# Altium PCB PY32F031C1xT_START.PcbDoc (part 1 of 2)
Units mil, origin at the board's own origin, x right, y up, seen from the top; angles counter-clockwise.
Board outline 1771.65 x 3929.06 mil, 2 copper layers (Top Layer, Bottom Layer), stack 21 mil thick; 137 components, 144 nets, 525 pads, 269 vias.
Unrouted connection lines stored in the file: 5.
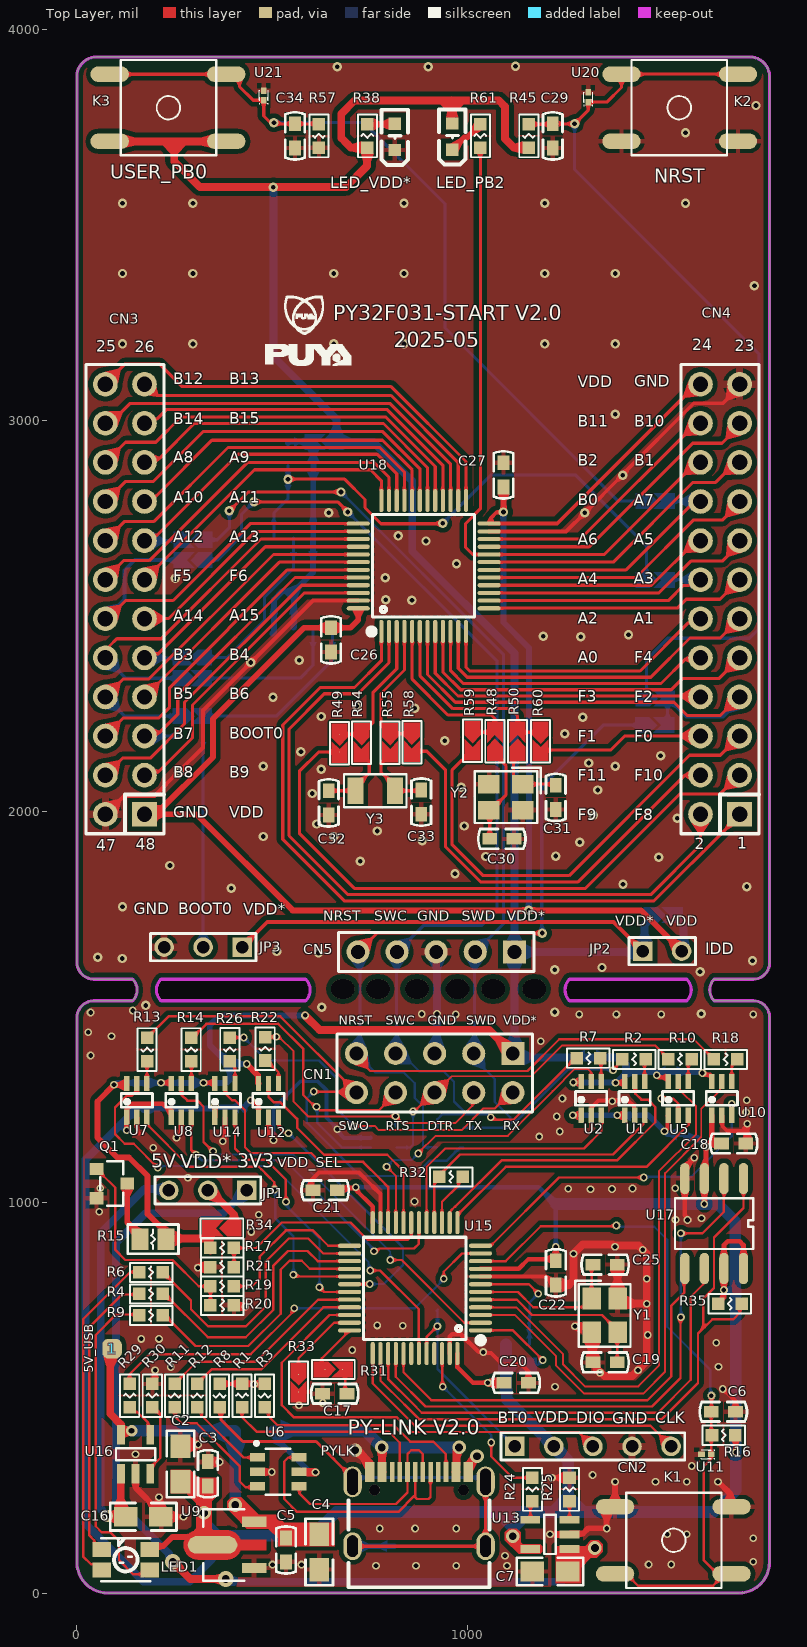
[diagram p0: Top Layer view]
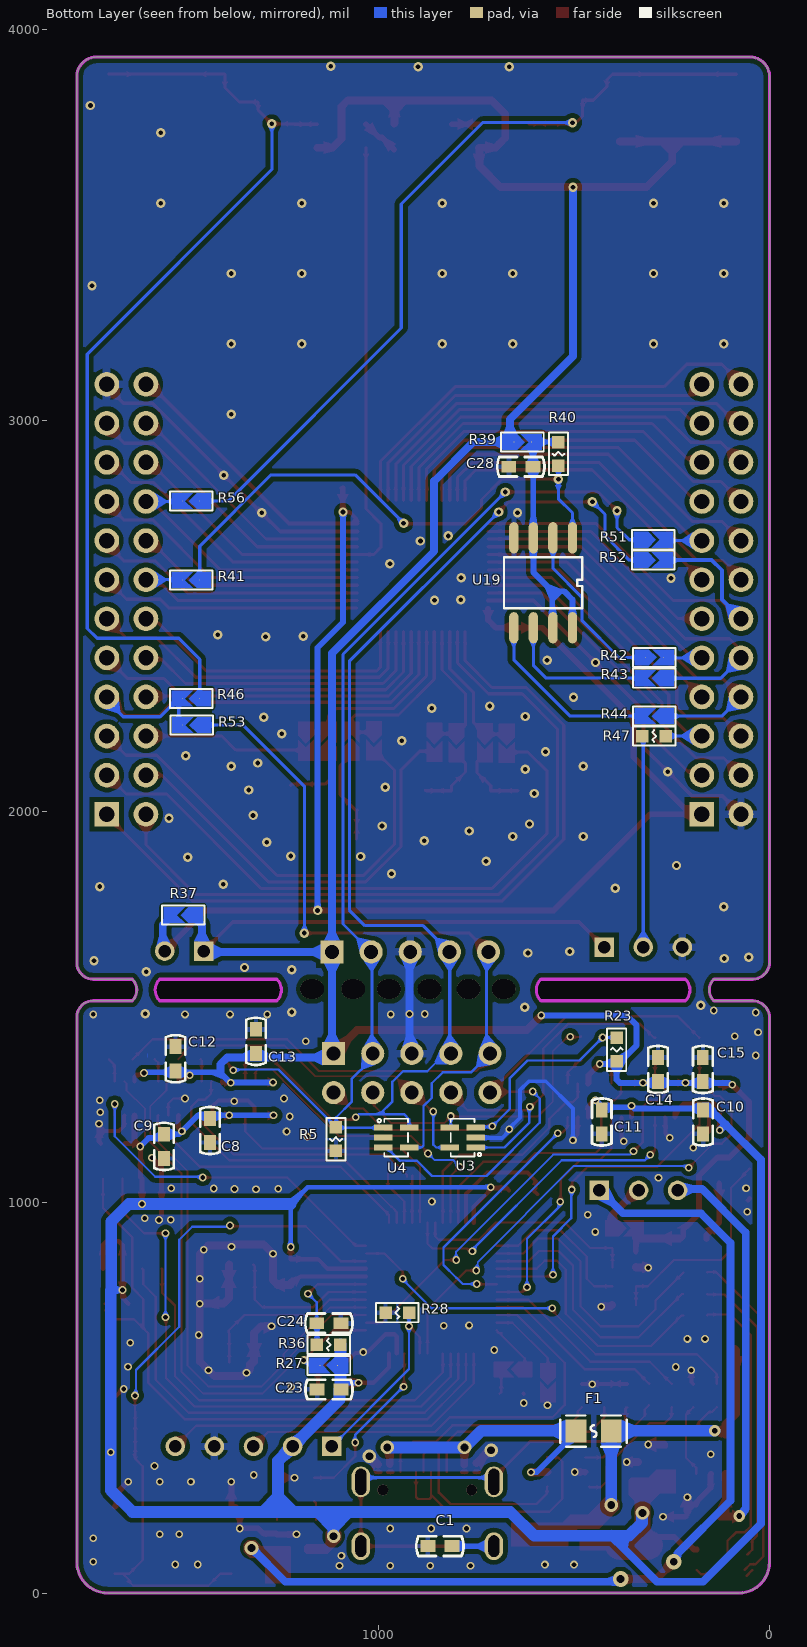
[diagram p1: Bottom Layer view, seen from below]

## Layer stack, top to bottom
Top Solder: solder mask 0.4, Solder Resist, Dk 3.5
Top Layer: signal copper 1.4
Dielectric 2: prepreg 2.8, Composite dielectric, Dk 4.1
Dielectric 1: prepreg 12.6, Composite dielectric, Dk 4.1
Dielectric 3: prepreg 2.8, Composite dielectric, Dk 4.1
Bottom Layer: signal copper 1.4
Bottom Solder: solder mask 0.4, Solder Resist, Dk 3.5

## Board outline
0,78.74 0,1470 cw(c43.75,1471.25) 42.5,1515 142.5,1515 ccw(c115,1542.5) 142.5,1570 42.5,1570 cw(c43.75,1613.75) 0,1615 0,3879.06 cw(c50,3879.06) 50,3929.06 1721.65,3929.06 cw(c1721.65,3879.06) 1771.65,3879.06 1771.65,1611.65 cw(c1730,1611.65) 1730,1570 1630,1570 ccw(c1657.5,1542.5) 1630,1515 1730,1515 cw(c1730,1473.35) 1771.65,1473.35 1771.65,78.74 cw(c1692.91,78.74) 1692.91,0 78.74,0 cw(c78.74,78.74)
cut-out: 1260,1515 cw(c1287.5,1542.5) 1260,1570 1560,1570 cw(c1532.5,1542.5) 1560,1515
cut-out: 215,1515 cw(c242.5,1542.5) 215,1570 585,1570 cw(c557.5,1542.5) 585,1515
cut-out: 215,1515 cw(c242.5,1542.5) 215,1570 585,1570 cw(c557.5,1542.5) 585,1515 565,1515
cut-out: 1260,1515 cw(c1287.5,1542.5) 1260,1570 1560,1570 cw(c1532.5,1542.5) 1560,1515

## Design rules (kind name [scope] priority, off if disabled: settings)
Clearance polygon [InPolygon] p1: gap=12 ignorepadtopadclearanceinfootprint=TRUE
Clearance [All] p2: gap=8 ignorepadtopadclearanceinfootprint=TRUE
HoleToHoleClearance [All] p1: gap=1 allowstackedmicrovias=TRUE
MinimumSolderMaskSliver [All] p1: minsoldermaskwidth=0
PlaneClearance [All] p1: clearance=8
PlaneConnect [All] p1: planeconnectstyle=Direct reliefexpansion=20 reliefentries=4 reliefconductorwidth=10 reliefairgap=10
PolygonConnect [All] p1: thpad.connectstyle=Relief thpad.reliefconductorwidth=20 thpad.reliefentries=4 thpad.polygonreliefangle="90 Angle" thpad.airgapwidth=10 smdpad.connectstyle=Relief smdpad.reliefconductorwidth=12 smdpad.reliefentries=4 smdpad.polygonreliefangle="90 Angle" smdpad.airgapwidth=10 via.connectstyle=Direct via.reliefconductorwidth=10 via.reliefentries=4 via.polygonreliefangle="90 Angle" via.airgapwidth=10
RoutingVias [All] p1: holewidth=28 width=50 viastyle="Through Hole" minholewidth=28 minwidth=50 maxholewidth=28 maxwidth=50
SilkToSilkClearance [All] p1: silktosilkclearance=0
SilkToSolderMaskClearance [IsPad] p1: minsilkscreentomaskgap=0 clearancetoexposedcopper=TRUE
SolderMaskExpansion [All] p1: expansion=4 istentingtop=FALSE
UnRoutedNet [All] p1: checkbadconnections=TRUE
Width [All] p1: maxlimit=100 minlimit=5 preferedwidth=8
23 further rules are at their usual default settings.

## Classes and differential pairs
component class PY32F031C1xT_START: 3 C26 C27 C28 C29 C30 C31 C32 C33 C34 CN3 CN4 CN5 JP2 JP3 K2 K3 LED_PB2 LED_VDD* R37 R38 R39 R40 R41 R42 R43 R44 R45 R46 R47 R48 R49 R50 R51 R52 R53 R54 R55 R56 R57 R58 R59 R60 R61 U18 U19 U20 U21 Y2 Y3
component class PY32F403C1xT_LINK: 1 C1 C2 C3 C4 C5 C6 C7 C8 C9 C10 C11 C12 C13 C14 C15 C16 C17 C18 C19 C20 C21 C22 C23 C24 C25 CN1 CN2 F1 JP1 K1 LED1 PYLK Q1 R1 R2 R3 R4 R5 R6 R7 R8 R9 R10 R11 R12 R13 R14 R15 R16 R17 R18 R19 R20 R21 R22 R23 R24 R25 R26 R27 R28 R29 R30 R31 R32 R33 R34 R35 R36 U1 U2 U3 U4 U5 U6 U7 U8 U9 U10 U11 U12 U13 U14 U15 U16 U17 Y1

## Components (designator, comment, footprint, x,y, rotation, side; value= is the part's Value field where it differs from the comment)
1 "TP_SIN" TP_SIN 90,625 r90 top
C1 "4.7nF" C0603 843,120 r180 bottom
C2 "10uF" C0805 265,330 r270 top
C3 "100nF" C0603 335,305 r270 top
C4 "10uF" C0805 620,105 r90 top
C5 "100nF" C0603 535,110 r90 top
C6 "100nF" C0603 1653.5,463.5 r180 top
C7 "10uF" C0805 1210,55 r0 top
C8 "100nF" C0603 1431,1183 r90 bottom value=104
C9 "100nF" C0603 1548.9,1142.3 r90 bottom value=104
C10 "100nF" C0603 170.2,1204.9 r90 bottom value=104
C11 "100nF" C0603 429,1204.9 r90 bottom value=104
C12 "100nF" C0603 1519.4,1366.6 r270 bottom value=104
C13 "100nF" C0603 1313.8,1411.1 r270 bottom value=104
C14 "100nF" C0603 285.5,1339.2 r270 bottom value=104
C15 "100nF" C0603 170.5,1339.2 r270 bottom value=104
C16 "10uF" C0805 170,195 r180 top
C17 "100nF" C0603 659.59,509.5 r0 top
C18 "100nF" C0603 1680,1150 r180 top value=104
C19 "22pF" C0603 1351.12,590 r0 top
C20 "100nF" C0603 1123.87,537.59 r180 top value=104
C21 "100nF" C0603 635,1030 r0 top value=104
C22 "100nF" C0603 1225.12,819 r90 top value=104
C23 "100nF" C0603 1126.74,520.58 r180 bottom value=104
C24 "100nF" C0603 1127,690 r0 bottom value=104
C25 "22pF" C0603 1351.12,840 r180 top
C26 "100nF" C0603 650,2438 r270 top
C27 "100nF" C0603 1091,2860 r270 top
C28 "100nF" C0603 636,2881 r180 bottom value=104
C29 "100nF" C0603 1217,3727 r90 top
C30 "22pF" C0603 1087,1929 r180 top
C31 "22pF" C0603 1225,2035 r90 top
C32 "22pF" C0603 644,2021 r270 top
C33 "22pF" C0603 881,2023 r90 top
C34 "100nF" C0603 558,3727 r90 top
CN1 "2X5P" HDR2X5 1115,1380 r180 top
CN2 "CON5" CON5 1120,375 r0 top
CN3 "CON 2X12" "CON 2X12" 123,2742 r90 top locked
CN4 "CON 2X12" "CON 2X12" 1645,2742 r90 top locked
CN5 "Header 5" HDR1X5 1119,1640 r180 top
F1 "JK-SMD0805-050-16V" F0805 450,414 r180 bottom
JP1 "CON3" CON3 435,1030 r180 top
JP2 "CON2" CON2 1447,1642 r0 top
JP3 "CON3" CON3 423,1652 r180 top
K1 "TS-KG02S-AT43F" SW-SMD_4P-L6.0-W6.0-P4.50-LS8.5 1527.55,134.7 r180 top
K2 "TS-KG02S-AT43F" SW-SMD_4P-L6.0-W6.0-P4.50-LS8.5 1540,3799.38 r0 top
K3 "TS-KG02S-AT43F" SW-SMD_4P-L6.0-W6.0-P4.50-LS8.5 235,3799 r180 top
LED1 "MHPA3528RGBCT" LED-ARRAY-SMD_4P-L3.5-W2.8-TL 125,85 r0 top
LED_PB2 "GREEN" 0603_LED 961,3740 r90 top
LED_VDD* "RED" 0603_LED 814,3739 r90 top
PYLK "KH-TYPE-C-16P" USB-C-SMD_KH-TYPE-C-16P 875.2,214.81 r0 top locked
Q1 "2302" SOT23 89.37,1047.4 r90 top value=SI2302
R1 "5.1K" R0603 422.49,504.99 r270 top
R2 "27R" R0603 1425.21,1365 r180 top
R3 "5.1K" R0603 480,505 r90 top
R4 "680R" R0603 190,765 r0 top
R5 "1M" R0603 1109,1161 r90 bottom
R6 "680R" R0603 190,820 r0 top
R7 "27R" R0603 1308.39,1368.1 r180 top
R8 "1M" R0603 365,505 r90 top
R9 "680R" R0603 190,710 r0 top
R10 "27R" R0603 1542.35,1365 r180 top
R11 "27R" R0603 250,505 r90 top
R12 "27R" R0603 307.5,505 r90 top
R13 "27R" R0603 179.66,1390.08 r90 top
R14 "27R" R0603 292.3,1390.1 r90 top
R15 "100R" R0805 195,905 r0 top
R16 "10K" R0603 1654.5,403.5 r0 top
R17 "20K" R0603 371.52,882.61 r180 top
R18 "27R" R0603 1659.49,1365 r180 top
R19 "100R" R0603 371.53,784.78 r0 top
R20 "100K" R0603 371.52,735.88 r180 top
R21 "10K" R0603 371.53,833.69 r0 top
R22 "27R" R0603 481.63,1392.11 r90 top
R23 "4.7K" R0603 391,1390 r270 bottom
R24 "4.7K" R0603 1165,265 r270 top
R25 "16K" R0603 1260,265 r270 top
R26 "27R" R0603 391.2,1390.7 r90 top
R27 "0R" JP2_SMD 1127,582 r180 bottom
R28 "10K" R0603 952,717.08 r0 bottom
R29 "4.7K" R0603 135,505 r270 top
R30 "16K" R0603 193,505 r270 top
R31 "0R" JP2_SMD 656.21,571.75 r180 top
R32 "680R" R0603 957.46,1064.37 r0 top
R33 "0R" JP2_SMD 566.96,537.4 r90 top
R34 "0R" JP2_SMD 371,933 r0 top
R35 "100K" R0603 1670,740 r180 top
R36 "10K" R0603 1127.6,635.62 r180 bottom
R37 "0R" JP2_SMD 1500,1734 r180 bottom
R38 "680R" R0603 743,3727 r270 top
R39 "0R/NC" JP2_SMD 632,2944 r0 bottom
R40 "100K" R0603 540,2914 r90 bottom
R41 "0R/NC" JP2_SMD 1479,2591 r180 bottom
R42 "0R/NC" JP2_SMD 295,2393 r0 bottom
R43 "0R/NC" JP2_SMD 294.99,2340 r180 bottom
R44 "0R/NC" JP2_SMD 294.99,2243 r180 bottom
R45 "10K" R0603 1156,3727 r90 top
R46 "0R" JP2_SMD 1479,2288 r180 bottom
R47 "10K" R0603 294.99,2192 r180 bottom
R48 "0R" JP2_SMD 1069,2179 r270 top
R49 "0R" JP2_SMD 672,2174 r90 top
R50 "0R" JP2_SMD 1127.31,2178.53 r270 top
R51 "0R" JP2_SMD 297,2694 r0 bottom
R52 "0R" JP2_SMD 297,2642 r0 bottom
R53 "0R" JP2_SMD 1478,2220 r180 bottom
R54 "0R" JP2_SMD 728,2175 r90 top
R55 "0R" JP2_SMD 801,2175 r90 top
R56 "0R" JP2_SMD 1479,2793 r180 bottom
R57 "1.5K" R0603 619,3727 r90 top
R58 "0R" JP2_SMD 857,2176 r90 top
R59 "0R" JP2_SMD 1012,2180 r90 top
R60 "0R" JP2_SMD 1186,2179 r90 top
R61 "680R" R0603 1032,3726.99 r270 top
U1 "74LVC1T45DW" SOT363 1426.64,1265 r0 top
U2 "74LVC1T45DW" SOT363 1315.21,1265 r0 top
U3 "ESD_6V1" ESD_SOT323-5L 785,1165 r90 bottom value=ESDALC6V1W5
U4 "ESD_6V1" ESD_SOT323-5L 955,1165 r270 bottom value=ESDALC6V1W5
U5 "74LVC1T45DW" SOT363 1538.06,1265 r0 top locked
U6 "USBLC6-2SC6" SOT23-6 515,310 r90 top
U7 "74LVC1T45DW" SOT363 153.55,1260 r0 top locked
U8 "74LVC1T45DW" SOT363 267.26,1260 r0 top
U9 "LM1117F-3.3" SOT-89-3_L4.5-W2.5-P1.50-LS4.2-BR 400.39,123.01 r0 top
U10 "74LVC1T45DW" SOT363 1649.49,1265 r0 top
U11 "ESDALC6V1-1U2" ESD_ST0201 1610,355 r180 top
U12 "74LVC1T45DW" SOT363 490.12,1260 r0 top
U13 "MT9700" SOT23-5 1210,150 r90 top
U14 "74LVC1T45DW" SOT363 378.69,1260 r0 top
U15 "PY32F403C1xT" LQFP-48_L7.0-W7.0-P0.50-LS9.0-BL 865,780 r90 top locked
U16 "MT9700" SOT23-5 150,355 r0 top
U17 "P25Q64SH" SOP-8P 1630,945 r180 top value=SST25VF020B
U18 "PY32F031C1xT6" LQFP-48_L7.0-W7.0-P0.50-LS9.0-BL 887,2627 r0 top locked
U19 "P25Q64SH" SOP-8P 579,2584 r0 bottom value=SST25VF020B
U20 "ESDALC6V1-1U2" ESD_ST0201 1308,3825.89 r90 top
U21 "ESDALC6V1-1U2" ESD_ST0201 478,3830.59 r90 top
Y1 "24MHz" CRYSTAL-SMD_4P-L3.2-W2.5-BL 1350.12,710 r270 top
Y2 "24MHz" CRYSTAL-SMD_4P-L3.2-W2.5-BL 1097.31,2035.53 r180 top
Y3 "32.768KHz" CRYSTAL-SMD_L3.2-W1.5-1 763.19,2052 r180 top value=X503225MSB2GI

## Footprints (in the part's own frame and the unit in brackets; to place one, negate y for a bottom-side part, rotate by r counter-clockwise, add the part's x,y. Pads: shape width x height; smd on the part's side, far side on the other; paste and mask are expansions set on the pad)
0603_LED [mil]
  rect 31.5x31.5 smd: 1(19,1) 2(-48,1)
  silkscreen extent -86,-33 55,35
C0603 [mil]
  rect 38x30 smd: 1(-31,0) 2(31,0)
  silkscreen extent -60,-25 60,25
C0805 [mil]
  rect 60x50 smd: 1(-45,0) 2(45,0)
  silkscreen extent -85,-35 85,35
CON2 [mil]
  rect 50x50 hole 32: 1(0,0)
  round 50 hole 32: 2(100,0)
  silkscreen extent -35,-35 135,35
CON3 [mil]
  rect 50x50 hole 32: 1(0,0)
  round 50 hole 32: 2(100,0) 3(200,0)
  silkscreen extent -35,-35 235,35
CON5 [mil]
  rect 50x50 hole 32: 1(0,0)
  round 50 hole 32: 2(100,0) 3(200,0) 4(300,0) 5(400,0)
  silkscreen extent -35,-35 435,35
"CON 2X12" [mm]
  rect 1.6x1.6 hole 1: 1(-19.05,-1.27)
  round 1.6 hole 1: 2(-19.05,1.27) 3(-16.51,-1.27) 4(-16.51,1.27) 5(-13.97,-1.27) 6(-13.97,1.27) 7(-11.43,-1.27) 8(-11.43,1.27) 9(-8.89,-1.27) 10(-8.89,1.27) 11(-6.35,-1.27) 12(-6.35,1.27) 13(-3.81,-1.27) 14(-3.81,1.27) 15(-1.27,-1.27) 16(-1.27,1.27) 17(1.27,-1.27) 18(1.27,1.27) 19(3.81,-1.27) 20(3.81,1.27) 21(6.35,-1.27) 22(6.35,1.27) 23(8.89,-1.27) 24(8.89,1.27)
  silkscreen extent -20.32,-2.54 10.16,2.54
CRYSTAL-SMD_4P-L3.2-W2.5-BL [mm]
  rect 1.4x1.2 smd: 1(-1.1,-0.85) 2(1.1,-0.85) 3(1.1,0.85) 4(-1.1,0.85)
  silkscreen extent -2.26,-1.91 2.03,1.68
CRYSTAL-SMD_L3.2-W1.5-1 [mm]
  rect 1.05x1.7 smd: 1(-1.275,0) 2(1.275,0)
  silkscreen extent -2.03,-1.08 2.03,1.08
ESD_SOT323-5L [mm]
  rect 0.4x1.2 smd mask+0.05: 1(-0.65,-0.85) 2(0,-0.85) 3(0.65,-0.85) 4(0.65,0.85) 5(-0.65,0.85)
  silkscreen extent -1.23,-1.21 1.23,0.77, body extent -1.15,-1.05 1.15,1.05, height 1.1
ESD_ST0201 [mm]
  rect 0.425x0.33 smd mask+0.05: 1(-0.312,0) 2(0.312,0)
  silkscreen extent -0.55,-0.3 0.33,0.3, body extent -0.34,-0.18 0.34,0.18, height 0.34
F0805 [mm]
  rect 1.335x1.5 smd paste-100 mask+0.051: 1(-1.142,0) 2(1.142,0)
  silkscreen extent -2.16,-1.02 2.16,1.02
HDR1X5 [mm] "Connector; Header; 5 Position"
  rect 1.5x1.5 hole 0.9: 1(0,0)
  round 1.5 hole 0.9: 2(2.54,0) 3(5.08,0) 4(7.62,0) 5(10.16,0)
  silkscreen extent -1.27,-1.27 11.43,1.27
HDR2X5 [mm] "Connector; Header; 4x2 Position"
  rect 1.5x1.5 hole 0.9: 1(0,0)
  round 1.5 hole 0.9: 2(0,2.54) 3(2.54,0) 4(2.54,2.54) 5(5.08,0) 6(5.08,2.54) 7(7.62,0) 8(7.62,2.54) 9(10.16,0) 10(10.16,2.54)
  silkscreen extent -1.27,-1.27 11.43,3.81
JP2_SMD [mil]
  round 1 smd: 1(21.75,0) 2(-23.03,0.03)
  Top Layer region: -49.77,20.03 -49.77,20.03 3.72,20.03 -16.28,0.03 3.72,-19.98 -49.78,-19.98 -49.78,-19.98
  Top Layer region: -6.25,0 13.75,20 49.75,20 49.75,-20 49.75,-20 13.75,-20
  silkscreen extent -55,-25 54,25
LED-ARRAY-SMD_4P-L3.5-W2.8-TL [mm]
  rect 1.2x0.95 smd: 1(1.55,0.665) 2(1.55,-0.665) 3(-1.55,-0.665) 4(-1.55,0.665)
  silkscreen extent -1.6,-1.4 1.6,1.4
LQFP-48_L7.0-W7.0-P0.50-LS9.0-BL [mm]
  oval 0.27x1.5 smd mask+0.05: 1(-2.75,-4.25) 2(-2.25,-4.25) 3(-1.75,-4.25) 4(-1.25,-4.25) 5(-0.75,-4.25) 6(-0.25,-4.25) 7(0.25,-4.25) 8(0.75,-4.25) 9(1.25,-4.25) 10(1.75,-4.25) 11(2.25,-4.25) 12(2.75,-4.25) 25(2.75,4.25) 26(2.25,4.25) 27(1.75,4.25) 28(1.25,4.25) 29(0.75,4.25) 30(0.25,4.25) 31(-0.25,4.25) 32(-0.75,4.25) 33(-1.25,4.25) 34(-1.75,4.25) 35(-2.25,4.25) 36(-2.75,4.25)
  oval 1.5x0.27 smd mask+0.05: 13(4.25,-2.75) 14(4.25,-2.25) 15(4.25,-1.75) 16(4.25,-1.25) 17(4.25,-0.75) 18(4.25,-0.25) 19(4.25,0.25) 20(4.25,0.75) 21(4.25,1.25) 22(4.25,1.75) 23(4.25,2.25) 24(4.25,2.75) 37(-4.25,2.75) 38(-4.25,2.25) 39(-4.25,1.75) 40(-4.25,1.25) 41(-4.25,0.75) 42(-4.25,0.25) 43(-4.25,-0.25) 44(-4.25,-0.75) 45(-4.25,-1.25) 46(-4.25,-1.75) 47(-4.25,-2.25) 48(-4.25,-2.75)
  silkscreen extent -3.59,-4.46 3.3,3.34
R0603 [mil]
  rect 32x32 smd: 1(-30,0) 2(30,0)
  silkscreen extent -55,-24 54,25
R0805 [mm]
  rect 1.1x1.4 smd: 1(-0.85,0) 2(0.85,0)
  silkscreen extent -1.65,-0.95 1.65,0.95
SOP-8P [mil]
  oval 24x80 smd: 1(-75,-115) 2(-25,-115) 3(25,-115) 4(75,-115) 5(75,115) 6(25,115) 7(-25,115) 8(-75,115)
  silkscreen extent -100,-65 100,65
SOT23 [mm]
  rect 0.8x0.9 smd: 1(0.95,1) 2(-0.95,1) 3(0,-1)
  silkscreen extent -1.45,-0.75 1.45,0.75
SOT23-5 [mil]
  rect 20x50 smd: 1(-37.5,-50) 2(0,-50) 3(37.5,-50) 4(37.5,50) 5(-37.5,50)
  silkscreen extent -50,-15 50,15
SOT23-6 [mm]
  rect 0.55x1 smd: 1(0.95,1.35) 2(0,1.35) 3(-0.95,1.35) 4(-0.95,-1.35) 5(0,-1.35) 6(0.95,-1.35)
  silkscreen extent -1.5,-0.8 1.96,1.52
SOT363 [mm]
  rect 0.35x1 smd: 1(-0.65,-1.1) 2(0,-1.1) 3(0.65,-1.1) 4(0.65,1.1) 5(0,1.1) 6(-0.65,1.1)
  silkscreen extent -1.02,-0.45 1.02,0.45, body extent -1,-1.1 1,1.16, height 1
SOT-89-3_L4.5-W2.5-P1.50-LS4.2-BR [mm]
  rect 1.575x0.672 smd: 1(1.356,-1.5) 3(1.356,1.5)
  oval 3.226x1.14 smd: 2(-1.356,0)
  Top Layer region: -2.283,0.95 -0.429,0.95 -0.384,0.949 -0.34,0.946 -0.296,0.94 -0.252,0.933 -0.208,0.924 -0.165,0.912 -0.123,0.899 -0.081,0.884 -0.04,0.866 0,0.847 0.04,0.826 0.078,0.803 0.115,0.779 0.151,0.752 0.185,0.724 0.219,0.695 0.251,0.664 0.281,0.631 0.31,0.597 0.337,0.562 0.362,0.525 0.386,0.488 0.408,0.449 0.428,0.409 0.447,0.33 2.144,0.33 2.144,-0.33 0.447,-0.33 0.428,-0.409 0.408,-0.449 0.386,-0.488 0.362,-0.526 0.337,-0.562 0.31,-0.597 0.281,-0.631 0.251,-0.664 0.219,-0.695 0.185,-0.725 0.151,-0.753 0.115,-0.779 0.078,-0.804 0.04,-0.827 0,-0.848 -0.04,-0.867 -0.081,-0.884 -0.123,-0.899 -0.165,-0.913 -0.208,-0.924 -0.252,-0.934 -0.296,-0.941 -0.34,-0.946 -0.384,-0.949 -0.429,-0.95 -2.283,-0.95 -2.328,-0.949 -2.372,-0.946 -2.416,-0.941 -2.46,-0.934 -2.504,-0.924 -2.547,-0.913 -2.589,-0.899 -2.631,-0.884 -2.672,-0.867 -2.713,-0.848 -2.752,-0.827 -2.79,-0.804 -2.827,-0.779 -2.863,-0.753 -2.898,-0.725 -2.931,-0.695 -2.963,-0.664 -2.993,-0.631 -3.022,-0.597 -3.049,-0.562 -3.075,-0.526 -3.098,-0.488 -3.12,-0.449 -3.141,-0.409 -3.159,-0.369 -3.175,-0.327 -3.189,-0.285 -3.202,-0.242 -3.212,-0.199 -3.22,-0.155 -3.227,-0.111 -3.231,-0.067 -3.233,-0.022 -3.233,0.022 -3.231,0.067 -3.227,0.111 -3.22,0.155 -3.212,0.199 -3.202,0.242 -3.189,0.285 -3.175,0.327 -3.159,0.369 -3.141,0.409 -3.12,0.449 -3.098,0.488 -3.075,0.525 -3.049,0.562 -3.022,0.597 -2.993,0.631 -2.963,0.664 -2.931,0.695 -2.898,0.724 -2.863,0.752 -2.827,0.779 -2.79,0.803 -2.752,0.826 -2.713,0.847 -2.672,0.866 -2.631,0.884 -2.589,0.899 -2.547,0.912 -2.504,0.924 -2.46,0.933 -2.416,0.94 -2.372,0.946 -2.328,0.949 -2.283,0.95
  silkscreen extent -1.95,-2.33 0.7,2.33
SW-SMD_4P-L6.0-W6.0-P4.50-LS8.5 [mm]
  oval 2.5x1 smd: 1(-3.734,2.177) 2(3.835,2.177) 3(-3.734,-2.184) 4(3.835,-2.184)
  silkscreen extent -3.08,-3.1 3.12,3.09, body extent -4.48,-3 4.52,3, height 8.95
TP_SIN [mil]
  rrect60% 50x50 smd: 1(0,0)
USB-C-SMD_KH-TYPE-C-16P [mm]
  oval 1.2x2 hole 0.7 slot 1.7 at 90 deg: 1(-4.32,1.765) 2(4.32,1.765)
  oval 1.2x1.8 hole 0.7 slot 1.4 at 90 deg: 3(-4.32,-2.415) 4(4.32,-2.415)
  rect 0.3x1.3 smd: A1(-3.35,2.415) A4(-2.55,2.415) A5(-1.25,2.415) A6(-0.25,2.415) A7(0.25,2.415) A8(1.25,2.415) A9(2.55,2.415) A12(3.35,2.415) B1(3.05,2.415) B4(2.25,2.415) B5(1.75,2.415) B6(0.75,2.415) B7(-0.75,2.415) B8(-1.75,2.415) B9(-2.25,2.415) B12(-3.05,2.415)
  round 0.7 hole 0.7 unplated: ""(-2.89,1.235) ""(2.89,1.235)
  silkscreen extent -4.57,-5.08 4.57,0.57

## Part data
C1 C3 C5 C6 C17 C19 C25 C26 C27 C29 C30 C31 C34: library part C0603
C2 C4 C7 C16: library part C0805
C8 C9 C10 C11 C12 C13 C14 C15 C18 C20 C21 C22 C23 C24 C28: library part 贴片高压陶瓷电容, "Capacitor (Semiconductor SIM Model)"
C32 C33: library part Cap, "Capacitor"
CN1: Color=黑色, Current Rating (Max)=-, JLCPCB Part Class="Extended Part", LCSC Part Name="间距:2.54mm 2x5P 直插 方针", Manufacturer=XFCN(兴飞), Manufacturer Part=PZ254V-12-10P, Operating Temperature Range=-40℃~+105℃
CN3 CN4: library part CON2X12
CN5: "Header, 5-Pin"
F1: Current - Max=100A, Hold Current=500mA, JLCPCB Part Class="Extended Part", LCSC Part Name="6V 0.5A 贴片自恢复", Manufacturer=JK(金科), Operating Temperature=-40℃~+85℃, Power Dissipation=600mW, Resistance - Initial (Ri) (Min)=150mΩ, Resistance - Post Trip (R1) (Max)=850mΩ, Trip Current=1A, Voltage - Max=6V
JP2: library part CON2_DIP
K1 K2 K3: Actuator/Cap Color=黑色, Contact Current=50mA, Insulation Resistance=100MΩ, JLCPCB Part Class=扩展库, LCSC Part Name="6*6*4.3mm 立贴 轻触开关", Manufacturer=HANBO(汉博), Operating Force=250gf, Voltage Rating (DC)=12V
LED1: JLCPCB Part Class=扩展库, LCSC Part Name=RGB三色, Manufacturer=MEIHUA(美华)
LED_PB2 LED_VDD*: library part PDI-E803_Dup1
PYLK: BOM_JLCPCB Part Class="Extended Part", BOM_Manufacturer="Shenzhen Kinghelm Elec"
Q1: library part "MOSFET N", "MOSFET N"
R1 R2 R3 R4 R5 R6 R7 R8 R9 R10 R11 R12 R13 R14 R16 R17 R18 R19 R20 R21 R22 R23 R24 R26 R27 R28 R29 R31 R32 R33 R34 R35 R36 R37 R38 R39 R40 R41 R42 R43 R44 R45 R46 R47 R48 R49 R50 R51 R52 R53 R54 R55 R56 R57 R58 R59 R60 R61: library part R0603
R15: library part R0805
R25 R30: library part R0603_7, "0603WAF1602T5E 16KΩ(1602) ±1%"
U3 U4: library part ESDALC6V1W5, "Dual Transil array for ESD protection", Manufacturer=STMICROELECTRONICS
U11 U20 U21: "ESD protection 6V1", Manufacturer=STMICROELECTRONICS
U15 U18: "LQFP48", BOM_Manufacturer=PUYA(普冉)
U17 U19: library part SST25VF010, "SST25VF010"
Y1 Y2: library part ABM8AIG-24.000MHZ-82Z-T, "±20ppm , 12.5pF , T_use: -40°C~125°C", Equivalent Series Resistance (ESR)=50Ω, External load capacitor=8pF, Frequency Stability(Full temperature range)=±50ppm, JLCPCB Part Class="Extended Part", LCSC Part Name="24MHz ±20ppm 8pF", Manufacturer=ABRACON, Normal temperature Frequency Tolerance=±20ppm, Operating Temperature=-40℃~+125℃
Y3: library part CRYSTAL_1, "Crystal"

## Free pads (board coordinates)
  oval 60x50 hole 50 slot 60 at 0 deg unplated: 1(680,1545) 1(770,1545) 1(870,1545) 1(973.55,1545) 1(1065,1545) 1(1170,1545)

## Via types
v1: diameter 19.68, hole 11.81, Top Layer to Bottom Layer, tented both sides, 116 vias
v2: diameter 24, hole 12, Top Layer to Bottom Layer, tented both sides, 99 vias
v3: diameter 19.68, hole 11.81, Top Layer to Bottom Layer, 42 vias
v4: diameter 35, hole 20, Top Layer to Bottom Layer, tented both sides, 8 vias
v5: diameter 30, hole 15, Top Layer to Bottom Layer, tented both sides, 2 vias
v6: diameter 40, hole 20, Top Layer to Bottom Layer, tented both sides, 2 vias

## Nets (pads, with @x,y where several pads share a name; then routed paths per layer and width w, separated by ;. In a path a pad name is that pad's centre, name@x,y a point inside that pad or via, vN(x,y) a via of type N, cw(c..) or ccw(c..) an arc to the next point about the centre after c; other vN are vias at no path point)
3.3V_OUT_EN: R24.1 U15.46 | length 443
  Top Layer w6: U15.46@933.9,612.68 934.79,611.79 934.79,529.21 v1(936,528) ; v1(1060,385) 1060,349.4 1114.4,295 R24.1@1165,295
  Bottom Layer w6: v1(936,528) 1060,404 v1(1060,385)
3V3_PYLK: C2.2 C3.2 C8.2 C9.2 C10.2 C11.2 C18.2 C20.2 C21.2 C22.2 C23.2 CN2.2 LED1.1 R16.2 R27.1 R35.2 R36.2 U1.1 U2.1 U5.1 U7.1 U8.1 U9.2 U10.1 U12.1 U13.5 U14.1 U15.9 U15.24 U15.48 U17.3 U17.7 U17.8 | length 7852.3
  Top Layer w10: v1(445.16,1260.63) 449.42,1260.63 464.53,1245.52 U12.1@464.53,1216.69 ; C21.2@666,1030 C21.2@670.66,1034.66 ; C22.2@1225,854.12 v1(1225,885) ; v1(1685,360) 1685,401 R16.2@1686,402
  Top Layer w11: v1@710,1035 756.73,988.27 U15.24@756.73,947.32 ; U15.48@973.27,612.68 973.27,577.73 1013,538 v1(1051.39,538) ; U15.9@1032.32,829.21 1130.39,829.21 1155.3,854.12 C22.2@1225,854.12
  Top Layer w12: v3(127.35,1183.66) 127.96,1184.27 U7.1@127.96,1216.69 127.96,1237.87 141.96,1251.88 219.81,1251.88 241.67,1230.01 U8.1@241.67,1216.69 ; U14.1@353.1,1216.69 353.99,1217.58 353.12,1218.46 v1(353.12,1246.39) ; C21.2@670.66,1034.66 671.99,1035.99 710.99,1035.99 v1(713.28,1038.28) ; v1(1268.73,1222.03) 1269.06,1221.69 U2.1@1289.62,1221.69 ; v1(1382,1221.9) 1382.21,1221.69 U1.1@1401.05,1221.69 ; v3(1503.01,1181.02) 1512.47,1190.48 U5.1@1512.47,1221.69 1511.58,1220.8 U5.1@1511.8,1220.58 ; v1(1605,995) U17.3@1605,1060 1609.01,1064.01 1609.01,1141.25 v1(1609.87,1142.11) ; 1617.76,1150 C18.2@1649,1150 ; R35.2@1640,740 1655,755 v1(1655,775) U17.7@1655,830 1655,890 1665,900 1695,900 1705,890 U17.8@1705,830
  Top Layer w15: LED1.1@186.02,111.18 193.48,111.18 193.48,111.66 202.14,120.32 221.03,120.32 244.3,143.59 U9.2@313.8,143.59 ; v1(1609.87,1142.11) 1617.76,1150 1623.9,1156.14 U10.1@1623.9,1221.69
  Top Layer w20: v1@1054.87,537.59 C20.2@1092.87,537.59
  Bottom Layer w12: v1(713.28,1038.28) 1181.72,1038.28 1225,995 ; v1(1225,885) 1225,990 ; v1(1655,775) 1683.73,775 1684.65,775
  Bottom Layer w15: C10.2@170.2,1235.9 173.64,1239.34 346.07,1239.34 v1(353.12,1246.39) 356.92,1242.6 422.3,1242.6 C11.2@429,1235.9 429,1244.47 v1(445.16,1260.63) v1@443.56,1262.22 ; v1(1051.39,538) 1097.6,538 ; v1(1268.73,1222.03) 1462,1222.03 v3(1503.01,1181.02) 1510.73,1173.3 C9.2@1548.9,1173.3 ; C9.2@1558.32,1163.88 1588.1,1163.88 v1(1609.87,1142.11)
  Bottom Layer w20: v3(127.35,1183.66) 112.87,1198.15 111.65,1198.15 ; C10.2@170.2,1244.2 157.7,1244.2 111.65,1198.15 ; 405.3,146.25 287.88,28.84 170.16,28.84 22,177 22,1108.5 111.65,1198.15
  Bottom Layer w30: v4(325,205) 325.96,204.04 325.96,179.91 359.61,146.25 405.3,146.25 602.14,146.25 663.2,207.32 1115.96,207.32 ; C23.2@1095.74,520.58 C23.2@1097.6,520.58 ; R36.2@1097.6,635.62 1097.6,589.65 R27.1@1105.25,582 1097.6,574.35 1097.6,538 C23.2@1097.6,520.58 ; v4(1115,145) 1115.96,145.96 1115.96,207.32 ; 1225,995 v1(1605,995) 1638.96,995 1683.73,950.23 1683.73,775 ; 1684.65,775 1685,774.65 1685,263.15 1629.17,207.32 1257,207.32 ; C23.2@1097.6,520.58 1099.74,520.58 1099.74,495.26 1257,338 1257,207.32 ; 1115.96,207.32 1257,207.32
3V3_USB_PYLK: C7.2 JP1.1 U13.1 | length 2404.2
  Top Layer w20: v6@245.8,80 290.03,35.77 v6(380.96,35.77)
  Bottom Layer w20: v6(245,80) 245,85.41 235.27,95.14 235.27,100.98 100.1,236.16 100.1,895.86 175.6,971.36 374.6,971.36 418.24,1015 420,1015 433.24,1028.24 JP1.1@433.24,1030 ; v6(380.96,35.77) 387.82,28.91 1238.91,28.91 v4(1325,115) v4@1326.78,113.22
5V_OUT_EN: R29.1 U15.11 | length 1065.3
  Top Layer w6: R29.1@135,535 135,560 185.65,610.65 444.42,610.65 555.92,722.16 v1(555.92,728.42) ; v1(938.27,804.07) 938.27,821.87 984.98,868.58 U15.11@1032.32,868.58
  Bottom Layer w6: v1(555.92,728.42) 864.41,728.42 938.27,802.29 v1(938.27,804.07)
5V_USB_CHGR: 1.1 C4.2 C5.2 F1.2 U9.3 U16.5 | length 714.6
  Top Layer w20: 1.1@90,625 85.21,620.21 85.21,458.5 112.5,431.21 U16.5@112.5,405 ; U16.5@112.5,413.09 138.09,413.09 v5(140,415)
  Bottom Layer w30: v5(140,415) F1.2@404.02,415 ; v4(405,225) F1.2@405.02,414
5V_USB_PYLK: C16.2 JP1.3 U16.1 | length 1109.9
  Top Layer w20: v5(77.39,196.82) 78.3,195.91 124.09,195.91 C16.2@125,195 ; U16.1@112.5,304.69 112.5,290 112.19,289.69 112.19,210 C16.2@125,210
  Bottom Layer w20: v5(77.39,196.82) 74.92,197.32 71.21,201.03 69.81,202.43 60.92,215.77 60.92,921.89 172.85,1033.82 231.18,1033.82 JP1.3@235,1030
AD_TVDD: R17.1 R21.2 U15.19 | length 586.3
  Top Layer w6: R21.2@401.52,833.7 R17.1@401.52,882.61 458.79,882.61 523.97,947.79 699.66,947.79 743.59,903.86 846.86,903.86 855.16,912.17 U15.19@855.16,947.32
BOOT0: CN3.5 R47.2 U18.44 | length 830.9
  Top Layer w8: CN3.5@173,2192 182.5,2201.5 211.83,2201.5 257.91,2247.58 257.91,2297.62 557.76,2597.47 U18.44@719.68,2597.47
  Bottom Layer w8: CN3.5@173,2192 R47.2@260,2192
DIR_RESET: U10.5 U15.3 | length 1394.4
  Top Layer w5: U15.3@1032.32,711.1 1120.66,711.1 1160.03,671.73 1225.22,606.55 1225.22,582.77 1297.78,510.22 1448.12,510.22 1504.53,566.63 1504.53,1074.04 1596.97,1166.47 1596.97,1238.45 1645.1,1286.59 1645.1,1303.92 U10.5@1649.49,1308.31
DIR_RTCK_DTR: U5.5 U15.4 | length 1362.6
  Top Layer w5: U15.4@1032.32,730.79 1123.69,730.79 1163.06,691.42 1243.43,611.05 1243.43,584.49 1299.09,528.83 1435.95,528.83 1488.53,581.41 1488.53,1078.32 1583.97,1173.76 1583.97,1245.09 1542.45,1286.6 1542.45,1303.92 U5.5@1538.06,1308.31
DIR_TCK_SWCLK: U2.5 U15.21 | length 808
  Top Layer w5: v1(792.12,1090.67) 815.79,1067 U15.21@815.79,947.32 ; v3(873.49,1124.13) 873.49,1125.57 917.33,1169.41 1102.34,1169.41 1216.71,1283.79 1273.38,1340.46 1307.19,1340.46 1315.21,1332.43 U2.5@1315.21,1308.31
  Bottom Layer w5: v1(792.12,1090.67) 809.61,1108.16 857.52,1108.16 v3(873.49,1124.13)
DIR_TDI_VCP_TX: U12.5 U15.20 | length 603.7
  Top Layer w6: U12.5@490.12,1303.31 490.12,1268.77 503.92,1254.98 520.97,1254.98 563.25,1212.7 563.25,1189.92 632.11,1121.06 793.64,1121.06 835.47,1079.24 U15.20@835.47,947.32
DIR_TDO_SWO: U7.5 U15.43 | length 1250.3
  Top Layer w6: U7.5@153.55,1303.31 153.55,1284.73 140.19,1271.38 127.22,1271.38 97.4,1241.56 97.4,1174.28 122.48,1149.2 145.25,1149.2 v3(206.55,1087.9) ; v1(750,825) 775.69,825 874.84,725.85 U15.43@874.84,612.68
  Bottom Layer w5: v3(206.55,1087.9) 211.05,1092.41 500.21,1092.41 746.36,846.25 746.36,828.64 v1(750,825)
DIR_TMS_SWDIO: U1.5 U15.14 | length 784.3
  Top Layer w6: U15.14@953.58,947.32 953.58,973.99 956.95,977.36 956.95,978.29 966.51,987.85 967.44,987.85 1086.13,1106.54 1381.8,1106.54 1479.4,1204.13 1479.4,1243.36 1460.78,1261.98 1443.79,1261.98 1428.52,1277.25 1428.52,1306.42 U1.5@1426.64,1308.31
DIR_TRST_RTS: U8.5 U15.2 | length 1100.7
  Top Layer w6: U8.5@267.26,1303.31 267.85,1302.72 267.85,1274.24 282.53,1259.56 308.14,1259.56 323.94,1243.76 323.94,1153.79 v1(348.06,1129.67) ; v1(801.52,851.68) 830.72,851.68 990.98,691.42 U15.2@1032.32,691.42
  Bottom Layer w5: v1(348.06,1129.67) 356.33,1121.41 553.59,1121.41 801.52,873.48 v1(801.52,851.68)
DIR_VCP_RX: U14.5 U15.22 | length 688.5
  Top Layer w6: U14.5@378.69,1303.31 380.07,1301.93 380.07,1277.14 396.6,1260.6 404.2,1260.6 430,1234.81 430,1140.06 444.61,1125.45 599.3,1125.45 622.05,1102.71 732.18,1102.71 776.38,1058.51 796.1,1038.79 U15.22@796.1,947.32
F_VDD: C28.2 R39.2 R40.2 U19.3 U19.7 U19.8 | length 716.1
  Bottom Layer w12: R40.2@541.97,2943.97 606.97,2943.97
  Bottom Layer w15: U19.8@499.84,2453.79 504,2457.94 U19.8@504,2469 504,2541 525.39,2562.39 555.61,2562.39 ; R40.2@540,2942 R40.2@541.97,2943.97 ; U19.7@554,2469 555.61,2470.6 555.61,2562.39 ; R39.2@608.97,2943.97 606.97,2943.97 605,2942 C28.2@605,2881 604.5,2880.5 604.5,2699.5 U19.3@604,2699 604,2610.79 555.61,2562.39
GND: C1.1 C2.1 C3.1 C4.1 C5.1 C6.1 C7.1 C8.1 C9.1 C10.1 C11.1 C12.1 C13.1 C14.1 C15.1 C16.1 C17.1 C18.1 C19.1 C20.1 C21.1 C22.1 C23.1 C24.1 C25.1 C26.2 C27.1 C28.1 C29.1 C30.1 C31.1 C32.2 C33.1 C34.1 CN1.5 CN2.4 CN3.2 CN4.23 CN5.3 JP3.3 K1.3 K1.4 K2.3 K2.4 LED_VDD*.2 PYLK.A1 PYLK.A12 PYLK.B1 PYLK.B12 Q1.2 R1.1 R3.2 R5.1 R8.2 R20.1 R21.1 R25.1 R28.2 R30.1 R33.2 R57.1 U1.2 U2.2 U3.2 U4.2 U5.2 U6.2 U7.2 U8.2 U9.1 U10.2 U11.2 U12.2 U13.2 U14.2 U15.8 U15.23 U15.47 U16.2 U17.4 U18.23 U18.47 U19.4 U20.2 U21.2 Y1.2 Y1.4 Y2.2 Y2.4 | length 6343
  Top Layer w6: v1(1495,1265) 1525,1265 1538.06,1251.94 U5.2@1538.06,1221.69
  Top Layer w10: CN3.2@73,1992 120,2039 198.46,2039 v2(260.44,2100.98) 322.42,2162.96 322.42,2257.42 603.42,2538.42 U18.47@719.68,2538.42 ; U7.2@153.55,1216.69 154.54,1215.7 154.54,1180.08 159.36,1175.25 ; R30.1@195,535 200,540 v1(200,570) ; C16.1@210,210 210,200 C16.1@215,195 ; v1(255,1164.6) 265.89,1175.49 265.89,1215.32 U8.2@267.26,1216.69 ; C2.1@265,375 C2.1@270,380 ; C3.1@335,336 C3.1@336,335 ; R8.2@365,535 v1@453.95,535 ; v1(372.9,1155.7) 378.59,1161.39 U14.2@378.59,1216.59 ; R20.1@401.52,735.88 R20.1@403.04,737.4 ; v1(453.1,534.15) v1@453.95,535 ; R3.2@480,535 v1@453.95,535 ; U12.2@490.12,1216.69 491.41,1215.4 491.41,1172.62 501.83,1162.2 501.83,1156.83 v1@500,1155 ; C21.1@593.36,1020 603.36,1030 C21.1@604,1030 597.95,1036.05 597.95,1054.14 619.23,1075.42 721.98,1075.42 756.82,1040.58 ; C17.1@628.59,509.5 C17.1@629.59,510.5 ; PYLK.A1@743.31,309.89 PYLK.B12@755.12,309.89 ; PYLK.B1@995.28,309.89 PYLK.A12@1007.09,309.89 ; v1@1039.47,613.56 v1@1039.6,613.69 ; v1@1041.61,614.02 1059.36,614.02 1088.57,584.8 1137.07,584.8 1154.91,566.95 C20.1@1154.87,537.59 ; U18.23@1054.32,2715.58 1251.58,2715.58 v2(1299,2763) 1395,2859 v2(1396,2859) 1396,2861.37 1577.85,3043.22 1652.73,3043.22 1695,3085.49 CN4.23@1695,3092 ; U2.2@1314.26,1220.75 1317.1,1223.58 1317.1,1242.95 1334.15,1260 v1@1370.02,1260 ; v1(1369.2,1257.6) 1370.02,1258.42 v1@1370.02,1260 ; U1.2@1426.64,1221.69 1424.75,1223.58 1424.75,1245.25 1410,1260 v1@1370.02,1260 ; U10.2@1649.49,1221.69 1651.38,1219.8 1651.38,1193.96 1663.61,1181.72 1715,1181.72 ; v1(1651.81,522) 1654,522 1684.5,491.5 C6.1@1684.5,463.5
  Top Layer w11: 756.82,1040.58 776.42,1020.98 U15.23@776.42,947.32 ; U15.47@953.58,612.68 953.58,655.91 959.74,662.07 982.08,662.07 1027.87,616.28 v1(1039.35,616.28) ; U15.8@1032.32,809.53 1199.94,809.53 1221.47,788 C22.1@1225.12,788
  Top Layer w12: Q1.2@50.2,1009.8 Q1.2@55.01,1004.99 ; v1(1561.71,954.27) 1566.84,954.27 1555,966.11 1555,1088.88 1579.39,1113.27 v1(1579.39,1113.51) ; C18.1@1711,1150 1715,1154 1715,1181.72 v1(1715,1200)
  Top Layer w15: U16.2@149.48,304.48 150.91,303.04 150.91,269.09 C16.1@210,210 ; C16.1@215,195 v1(272.56,195) ; U6.2@470.66,310.05 472.24,308.47 473.29,309.52 v1(498.08,309.52) ; v1(1210,150) U13.2@1260,150 1262.16,152.16 1294.66,152.16 1308.23,165.74 v1@1354.26,165.74 ; v1(1215,295) R25.1@1260,295 ; v1(1355,165) 1355,209.44 1366.26,220.7 K1.4@1376.55,220.7 v1(1376.55,285) ; v1(1640,285) 1670.9,254.1 1670.9,224.34 K1.3@1674.55,220.7
  Top Layer w20: C16.1@210,210 v1(210,245) ; C2.1@270,380 v1(310,380) ; v1(309.83,832.29) 310.59,833.04 341.17,833.04 R21.1@341.93,833.8 ; C3.1@336,335 v1(365,335) ; R20.1@403.04,737.4 403.04,737.12 407.52,732.64 429.94,732.64 v1(430.7,731.87) ; v4(712.08,365) 716.13,365 723.63,357.5 724.15,357.5 PYLK.A1@749.14,332.52 ; CN1.5@915,1380 CN1.5@922.47,1387.47 ; PYLK.A12@1001.39,328.36 v4@1023.03,350 ; C22.1@1220.12,797 1225.12,792 C22.1@1225.12,788 1225.41,788.28 1258.41,788.28 1270.12,800 v1(1270.12,867.57) 1293.95,891.41 1370.41,891.41 v1(1376.26,885.55) 1377.35,885.55 1380.45,888.65 1436.47,888.65 v1(1447.03,878.1) 1457.58,867.54 v1(1457.58,803.85) 1457.58,740.13 1457.58,592.46 v1(1435.12,570) 1419.85,554.73 1349.89,554.73 v1@1339.64,564.98 ; v1(1273.98,682.29) 1301.06,682.29 Y1.2@1316.66,666.69 1318.39,664.96 1318.39,591.73 C19.1@1320.12,590 1324.12,590 1329.12,585 1329.12,575.5 1330.37,574.25 ; 1330.37,570.63 v1(1337.83,563.18) ; C25.1@1382.12,840 1382.85,839.27 1382.85,754.04 Y1.4@1383.59,753.31 1396.74,740.16 v1(1457.55,740.16)
  Bottom Layer w6: v1@499.26,1157.83 v1(502.89,1157.83)
  Bottom Layer w10: v1(502.89,1157.83) 502.89,1239.49 572.46,1309.06 615.72,1309.06 638,1286.78 638,1215.79 665.89,1187.9 v1(665.89,1185.89) ; v1@665,1183 683.72,1164.28 750.81,1164.28 U3.2@751.54,1165
  Bottom Layer w20: CN1.5@915,1380 921,1386 v3(921,1481) CN5.3@921,1637.82
  other v1: 765,70 867.5,70 970,70 1100,70 1462.25,73 1520,73 1730,80 1095,95 1730,140 1510,150 1560,150 775,165 865,165 970,165 1480,285 1560,285 1319,302 1573,325 150,355 1641,578.5 1635,640 165,650 210,650 1460.12,660 57.3,975.34 60,1035 1182.35,1167.57 1241.94,1264.95 35,1375 1285,1480 1380,1480 1495,1480 1730,1480 35,1485 143,1490
  other v2: 1597,1482 1222,1486 626,1498 176,1503 1594,1589 1222,1594 1343,1600 1728,1617 116,1623 53,1626 618,1637 511,1641 116.78,1755 395,1803 1713,1807 1397,1813 967,1840 238,1861 725,1872 1488,1882 1046,1884 1225,1885 1286,1920 883,1924 476.78,1935 656.78,1935 768,1949 991,1962 614,1967 1536,1982 1321,1989 602,2045 1332,2054 983.1,2061.13 625,2107 476.78,2115 1376.78,2115 1309,2123 1493,2142 573,2152 941,2180 1248,2198 1294,2240 625,2242 864,2263 716,2268.69 501.52,2291.39 445,2380 569,2386 1289,2446 1193,2447 1411,2451 857,2539 790,2541 252,2596 789,2597 971,2633 893,2691 821.99,2703.87 644.52,2763.39 1376.78,3015 116.78,3195 296.78,3195 656.78,3195 836.78,3195 1196.78,3195 1376.78,3195 1733,3344 116.78,3375 296.78,3375 656.78,3375 836.78,3375 1196.78,3375 1376.78,3375 116.78,3555 296.78,3555 836.78,3555 1196.78,3555 1556.78,3555 1556.78,3735 1737,3805 666,3904 899,3904 1122,3905
  other v3: 500.23,72.73 574.48,72.72 568,480 629,486 1223.05,527.77 239.93,578.18 704.43,621.59 833.63,683.94 768.47,684.5 445.71,923.68 1531.33,954.53 1597.76,958.38 464.86,967.62 863.55,1001.58 1313.59,1033.06 1368.58,1033.45 1256.66,1033.84 1421.24,1034.63 1530.67,1035.55 284,1062 195,1139 1235.29,1180.47 1227.19,1218.9 1711.69,1229.78 1713.32,1260.65 1186.59,1411.54 88.6,1424 29.3,1434.1 969,1480 882,1481
  other v4: 1023.55,350
L_USB_CN_DM: PYLK.A7 PYLK.B7 U6.4 | length 509.5
  Top Layer w6: U6.4@568.15,272.6 569.18,271.57 569.18,254.46 596.04,227.6 816.36,227.6 845.67,256.9 845.67,355.67 855,365 875,365 885.04,354.96 PYLK.A7@885.04,309.89
L_USB_CN_DP: PYLK.A6 PYLK.B6 U6.6 | length 675.7
  Top Layer w6: U6.6@568.15,347.4 567.26,346.51 540.39,346.51 530.35,336.47 530.35,240.4 563.22,207.53 822.27,207.53 862.55,247.81 863.63,248.89 864.95,250.21 865.09,249.78 865.15,249.57 ; 865.75,246.78 865.75,244.61 866.31,244.04 870.05,240.31 899.06,240.31 904.34,245.59 PYLK.B6@904.34,309.5 ; 865.75,247.38 PYLK.A6@865.75,309.5
LED_BLUE: R9.2 U15.28 | length 675.2
  Top Layer w6: R9.2@220,710 225.04,710 303.26,631.77 438.53,631.77 521.33,714.58 521.33,827.41 543.92,850 575,850 595.79,829.21 U15.28@697.68,829.21
LED_GREEN: R6.2 U15.26 | length 724.3
  Top Layer w6: R6.2@220,820 291.82,748.18 291.82,725.67 335.36,682.13 432.27,682.13 483.48,733.34 483.48,848.48 541.75,906.75 591.91,906.75 630.07,868.58 U15.26@697.68,868.58
LED_RED: R4.2 U15.27 | length 692.2
  Top Layer w6: R4.2@220,765 224.07,765 335.03,654.04 432.13,654.04 502.68,724.59 502.68,837.68 540,875 590,875 616.1,848.9 U15.27@697.68,848.9
NetC1_2: C1.2 PYLK.1 PYLK.2 PYLK.3 PYLK.4 R8.1 | length 1402.2
  Top Layer w8: R8.1@365,475 368.29,471.71 368.29,443.87 424.64,387.52 611.97,387.52 705.12,294.37 PYLK.1@705.12,284.29 ; PYLK.3@705.12,119.73 PYLK.4@1045.28,119.73 PYLK.2@1045.28,284.29
  Bottom Layer w8: PYLK.1@716.04,295.21 PYLK.2@1034.36,295.21 ; C1.2@811.73,119.73 C1.2@812,120
  Bottom Layer w15: PYLK.3@705.12,119.73 C1.2@811.73,119.73
  Bottom Layer w20: PYLK.1@705.12,284.29 PYLK.1@716.04,295.21 ; PYLK.2@1034.36,295.21 PYLK.2@1045.28,284.29
NetC17_2: C17.2 R31.2 | length 64.1
  Top Layer w6: 686.21,571.75 686.21,513.88 C17.2@690.59,509.5
NetC29_2: C29.2 K2.1 K2.2 R45.2 R46.1 U20.1 | length 2527.2
  Top Layer w8: R45.2@1156,3757 1216,3757 C29.2@1217,3758 v2(1273,3758) 1308,3793 U20.1@1308,3813.59 1355.59,3813.59 1393,3851 K2.1@1393,3885.08 K2.2@1691,3885.08
  Bottom Layer w8: v2(1273,3758) 1273,3641 1745,3169 1745,2467 1720,2442 1511,2442 1457.25,2388.25 R46.1@1457.25,2288
NetC30_2: C30.2 R48.1 Y2.3 | length 250.5
  Top Layer w8: Y2.3@1054,2002.07 1056,2000.07 C30.2@1056,1929 ; Y2.3@1057.94,2002.07 1098,2042.13 1098,2115.84 1065.31,2148.53
NetC31_2: C31.2 R50.1 Y2.1 | length 189.8
  Top Layer w8: R50.1@1127.31,2156.78 1117,2146.48 1117,2093.31 1117.06,2093.25 1117.06,2088.62 1136.68,2069 1222,2069 C31.2@1225,2066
